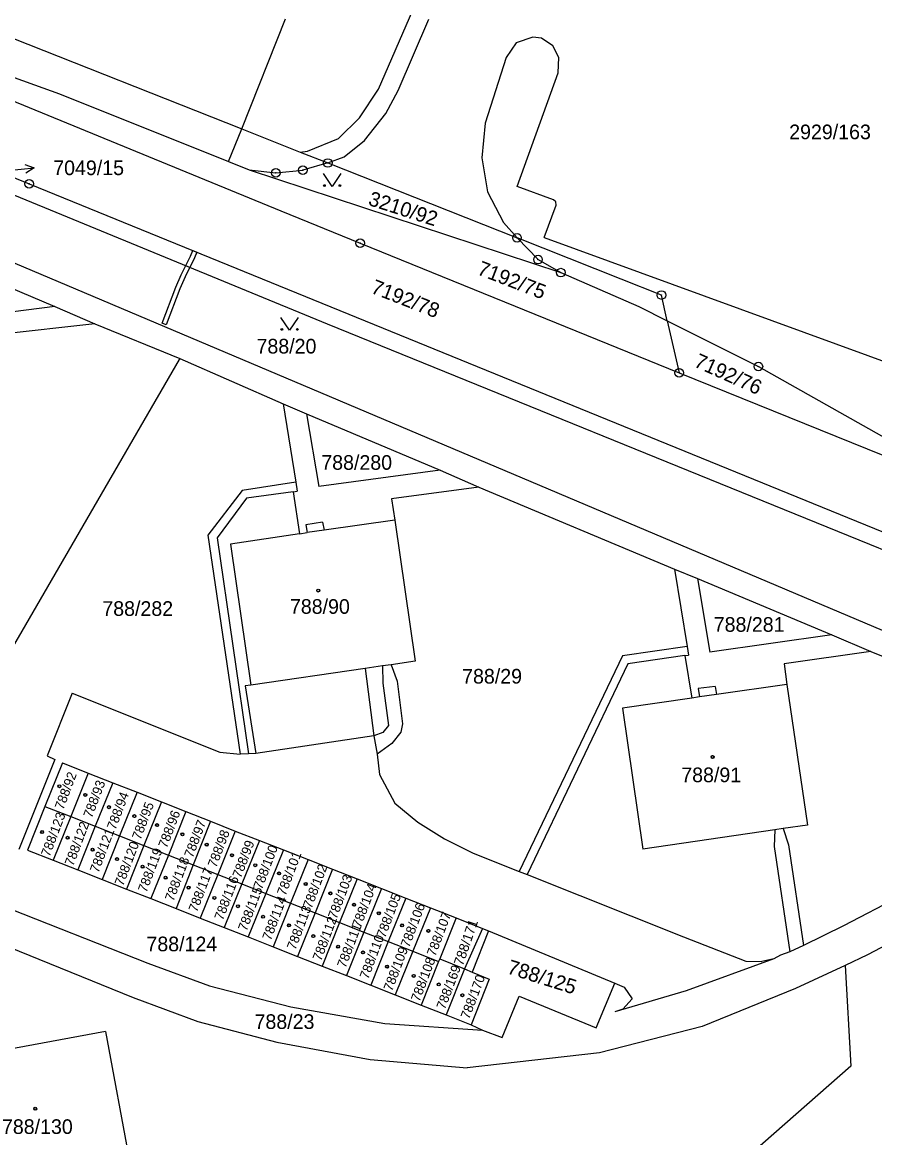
# Model space of a CAD drawing. Extents: x -593183 to -588034, y -1130415 to -1124994.
# Drawn here: x -591815.1 to -591716.1, y -1128430.1 to -1128300.6 of the extents above; entities that cross this region are included whole.
import ezdxf

# ---------------------------------------------------------------- set-up
doc = ezdxf.new("R2010")
doc.units = 0
for name, color, linetype in [('Vrstva 1', 7, 'Continuous'), ('Vrstva 16', 7, 'Continuous'), ('Vrstva 18', 7, 'Continuous'), ('Vrstva 19', 7, 'Continuous'), ('Vrstva 24', 7, 'Continuous'), ('Vrstva 25', 7, 'Continuous'), ('Vrstva 27', 7, 'Continuous'), ('Vrstva 4', 7, 'Continuous')]:
    doc.layers.add(name, color=color, linetype=linetype)

msp = doc.modelspace()

# ---------------------------------------------------------------- linework, layer by layer
at = {"layer": 'Vrstva 1'}
for p, q in [((-591955.86, -1128261.68), (-591814.3, -1128319.36)), ((-591931.29, -1128279.8), (-591692.48, -1128380.79)), ((-591864.93, -1128289.33), (-591810.78, -1128308.93)), ((-591849.68, -1128289.18), (-591789.62, -1128312.98)), ((-591841.44, -1128299.35), (-591785.07, -1128322.48)), ((-591789.62, -1128312.98), (-591784.53, -1128300.19)), ((-591771.45, -1128308.52), (-591767.88, -1128300.24)), ((-591757.76, -1128303), (-591758.9, -1128304.7)), ((-591755.84, -1128302.32), (-591757.76, -1128303)), ((-591754.8, -1128302.46), (-591755.84, -1128302.32)), ((-591753.51, -1128303.32), (-591754.8, -1128302.46)), ((-591752.79, -1128304.7), (-591753.51, -1128303.32)), ((-591758.9, -1128304.7), (-591761.37, -1128312.32)), ((-591752.9, -1128306.49), (-591752.79, -1128304.7)), ((-591757.64, -1128319.66), (-591752.9, -1128306.49)), ((-591772.9, -1128311.18), (-591771.45, -1128308.52)), ((-591845.27, -1128308.65), (-591779.71, -1128335.63)), ((-591810.78, -1128308.93), (-591791.16, -1128316.75)), ((-591775.38, -1128314.31), (-591772.9, -1128311.18)), ((-591761.37, -1128312.32), (-591761.76, -1128316.33)), ((-591791.16, -1128316.75), (-591789.62, -1128312.98)), ((-591789.62, -1128312.98), (-591782.83, -1128315.67)), ((-591777.71, -1128316.23), (-591775.38, -1128314.31)), ((-591782.83, -1128315.67), (-591779.62, -1128316.94)), ((-591779.62, -1128316.94), (-591777.71, -1128316.23)), ((-591761.76, -1128316.33), (-591761.1, -1128320.29)), ((-591791.16, -1128316.75), (-591788.74, -1128317.72)), ((-591779.62, -1128316.94), (-591757.66, -1128325.63)), ((-591788.74, -1128317.72), (-591752.58, -1128329.67)), ((-591814.3, -1128319.36), (-591692.65, -1128368.97)), ((-591753.41, -1128321.21), (-591757.64, -1128319.66)), ((-591761.1, -1128320.29), (-591759.21, -1128323.85)), ((-591753.14, -1128321.45), (-591753.41, -1128321.21)), ((-591753.12, -1128321.84), (-591753.14, -1128321.45)), ((-591785.07, -1128322.48), (-591775.88, -1128326.24)), ((-591754.51, -1128325.61), (-591753.12, -1128321.84)), ((-591759.21, -1128323.85), (-591757.66, -1128325.63)), ((-591775.88, -1128326.24), (-591738.82, -1128341.29)), ((-591745.55, -1128330.43), (-591757.66, -1128325.63)), ((-591754.51, -1128325.61), (-591693.43, -1128347.86)), ((-591827.42, -1128326.73), (-591811.33, -1128333.61)), ((-591752.58, -1128329.67), (-591743.52, -1128333.62)), ((-591740.9, -1128332.27), (-591745.55, -1128330.43)), ((-591740.21, -1128335.28), (-591740.9, -1128332.27)), ((-591811.33, -1128333.61), (-591806.67, -1128335.61)), ((-591743.52, -1128333.62), (-591740.21, -1128335.28)), ((-591806.67, -1128335.61), (-591817.81, -1128336.86)), ((-591806.67, -1128335.61), (-591796.81, -1128339.62)), ((-591779.71, -1128335.63), (-591717.97, -1128360.71)), ((-591740.21, -1128335.28), (-591738.82, -1128341.29)), ((-591740.21, -1128335.28), (-591729.64, -1128340.58)), ((-591796.81, -1128339.62), (-591796.87, -1128339.76)), ((-591796.81, -1128339.62), (-591784.8, -1128344.89)), ((-591796.87, -1128339.76), (-591824.71, -1128387.77)), ((-591729.64, -1128340.58), (-591712.55, -1128350.2)), ((-591738.82, -1128341.29), (-591715.2, -1128350.88)), ((-591784.8, -1128344.89), (-591782.1, -1128346.07)), ((-591784.8, -1128344.89), (-591783.34, -1128353.98)), ((-591782.1, -1128346.07), (-591766.57, -1128352.62)), ((-591766.57, -1128352.62), (-591762.08, -1128354.56)), ((-591783.63, -1128355.1), (-591783.2, -1128355.06)), ((-591783.63, -1128355.1), (-591782.9, -1128359.98)), ((-591783.34, -1128353.98), (-591783.2, -1128355.06)), ((-591762.08, -1128354.56), (-591772.22, -1128355.95)), ((-591762.08, -1128354.56), (-591739.38, -1128364.1)), ((-591772.22, -1128355.95), (-591771.86, -1128358.42)), ((-591780.25, -1128358.65), (-591782.16, -1128358.94)), ((-591782.16, -1128358.94), (-591782.01, -1128359.86)), ((-591780.25, -1128358.65), (-591780.04, -1128359.58)), ((-591771.86, -1128358.42), (-591780.04, -1128359.58)), ((-591771.86, -1128358.42), (-591769.48, -1128374.79)), ((-591782.9, -1128359.98), (-591790.93, -1128361.21)), ((-591782.9, -1128359.98), (-591782.01, -1128359.86)), ((-591790.93, -1128361.21), (-591788.56, -1128377.56)), ((-591717.97, -1128360.71), (-591690.26, -1128371.89)), ((-591739.38, -1128364.1), (-591736.72, -1128365.2)), ((-591739.38, -1128364.1), (-591737.91, -1128373.07)), ((-591736.72, -1128365.2), (-591721.12, -1128371.71)), ((-591721.12, -1128371.71), (-591716.57, -1128373.65)), ((-591737.91, -1128373.07), (-591737.75, -1128374.07)), ((-591738.16, -1128374.13), (-591737.75, -1128374.07)), ((-591738.16, -1128374.13), (-591737.35, -1128379.07)), ((-591716.57, -1128373.65), (-591726.66, -1128375.09)), ((-591716.57, -1128373.65), (-591693.55, -1128383.16)), ((-591775.28, -1128375.63), (-591788.56, -1128377.56)), ((-591773.28, -1128375.34), (-591775.28, -1128375.63)), ((-591775.28, -1128375.63), (-591774.3, -1128383.46)), ((-591772.26, -1128375.19), (-591773.28, -1128375.34)), ((-591769.48, -1128374.79), (-591772.26, -1128375.19)), ((-591726.66, -1128375.09), (-591726.33, -1128377.49)), ((-591809.3, -1128378.49), (-591812.2, -1128385.77)), ((-591809.3, -1128378.49), (-591792.14, -1128385.34)), ((-591788.56, -1128377.56), (-591789.2, -1128377.65)), ((-591789.2, -1128377.65), (-591787.97, -1128385.49)), ((-591734.65, -1128377.71), (-591736.62, -1128377.95)), ((-591736.62, -1128377.95), (-591736.46, -1128378.93)), ((-591734.65, -1128377.71), (-591734.51, -1128378.65)), ((-591726.33, -1128377.49), (-591734.51, -1128378.65)), ((-591726.33, -1128377.49), (-591723.94, -1128393.83)), ((-591737.35, -1128379.07), (-591745.42, -1128380.22)), ((-591736.46, -1128378.93), (-591737.35, -1128379.07)), ((-591745.42, -1128380.22), (-591743.06, -1128396.59)), ((-591774.3, -1128383.46), (-591773.89, -1128385.57)), ((-591811.3, -1128386.19), (-591815.5, -1128396.64)), ((-591812.2, -1128385.77), (-591811.3, -1128386.19)), ((-591792.14, -1128385.34), (-591789.81, -1128385.57)), ((-591788.82, -1128385.52), (-591789.81, -1128385.57)), ((-591787.97, -1128385.49), (-591788.82, -1128385.52)), ((-591773.89, -1128385.57), (-591773.63, -1128387.93)), ((-591810.43, -1128386.59), (-591812.46, -1128391.65)), ((-591810.43, -1128386.59), (-591807.43, -1128387.77)), ((-591807.43, -1128387.77), (-591809.46, -1128392.83)), ((-591807.43, -1128387.77), (-591804.59, -1128388.89)), ((-591773.63, -1128387.93), (-591771.84, -1128391.28)), ((-591804.59, -1128388.89), (-591806.62, -1128393.95)), ((-591804.59, -1128388.89), (-591801.77, -1128390)), ((-591801.77, -1128390), (-591803.8, -1128395.06)), ((-591801.77, -1128390), (-591798.94, -1128391.11)), ((-591798.94, -1128391.11), (-591800.97, -1128396.18)), ((-591798.94, -1128391.11), (-591796.1, -1128392.23)), ((-591771.84, -1128391.28), (-591769.16, -1128393.47)), ((-591812.46, -1128391.65), (-591814.49, -1128396.71)), ((-591812.46, -1128391.65), (-591809.46, -1128392.83)), ((-591796.1, -1128392.23), (-591798.13, -1128397.29)), ((-591796.1, -1128392.23), (-591793.26, -1128393.35)), ((-591809.46, -1128392.83), (-591811.5, -1128397.89)), ((-591809.46, -1128392.83), (-591806.62, -1128393.95)), ((-591806.62, -1128393.95), (-591808.66, -1128399.01)), ((-591806.62, -1128393.95), (-591803.8, -1128395.06)), ((-591793.26, -1128393.35), (-591795.25, -1128398.42)), ((-591793.26, -1128393.35), (-591790.36, -1128394.5)), ((-591769.16, -1128393.47), (-591766.06, -1128395.42)), ((-591723.94, -1128393.83), (-591726.75, -1128394.2)), ((-591803.8, -1128395.06), (-591805.82, -1128400.12)), ((-591803.8, -1128395.06), (-591800.97, -1128396.18)), ((-591790.36, -1128394.5), (-591792.4, -1128399.55)), ((-591790.36, -1128394.5), (-591787.57, -1128395.59)), ((-591727.73, -1128394.35), (-591743.06, -1128396.59)), ((-591726.75, -1128394.2), (-591727.73, -1128394.35)), ((-591800.97, -1128396.18), (-591802.99, -1128401.24)), ((-591800.97, -1128396.18), (-591798.13, -1128397.29)), ((-591787.57, -1128395.59), (-591789.61, -1128400.64)), ((-591787.57, -1128395.59), (-591784.78, -1128396.69)), ((-591766.06, -1128395.42), (-591762.73, -1128397.07)), ((-591843.22, -1128397.22), (-591802.21, -1128413.82)), ((-591814.49, -1128396.71), (-591811.5, -1128397.89)), ((-591811.5, -1128397.89), (-591808.66, -1128399.01)), ((-591798.13, -1128397.29), (-591800.16, -1128402.35)), ((-591798.13, -1128397.29), (-591795.25, -1128398.42)), ((-591784.78, -1128396.69), (-591786.82, -1128401.74)), ((-591784.78, -1128396.69), (-591781.92, -1128397.82)), ((-591781.92, -1128397.82), (-591783.94, -1128402.88)), ((-591781.92, -1128397.82), (-591779.07, -1128398.94)), ((-591762.73, -1128397.07), (-591757.39, -1128399.2)), ((-591808.66, -1128399.01), (-591805.82, -1128400.12)), ((-591795.25, -1128398.42), (-591797.24, -1128403.5)), ((-591795.25, -1128398.42), (-591792.4, -1128399.55)), ((-591779.07, -1128398.94), (-591781.1, -1128404)), ((-591779.07, -1128398.94), (-591776.23, -1128400.06)), ((-591757.39, -1128399.2), (-591756.48, -1128399.56)), ((-591825.32, -1128400.06), (-591800.51, -1128409.83)), ((-591805.82, -1128400.12), (-591802.99, -1128401.24)), ((-591792.4, -1128399.55), (-591794.44, -1128404.6)), ((-591792.4, -1128399.55), (-591789.61, -1128400.64)), ((-591776.23, -1128400.06), (-591778.25, -1128405.12)), ((-591776.23, -1128400.06), (-591773.4, -1128401.18)), ((-591756.48, -1128399.56), (-591738.34, -1128406.79)), ((-591802.99, -1128401.24), (-591800.16, -1128402.35)), ((-591789.61, -1128400.64), (-591791.65, -1128405.7)), ((-591789.61, -1128400.64), (-591786.82, -1128401.74)), ((-591786.82, -1128401.74), (-591788.87, -1128406.8)), ((-591786.82, -1128401.74), (-591783.94, -1128402.88)), ((-591773.4, -1128401.18), (-591775.43, -1128406.23)), ((-591773.4, -1128401.18), (-591770.57, -1128402.29)), ((-591712.43, -1128401.69), (-591719.74, -1128405.5)), ((-591800.16, -1128402.35), (-591797.24, -1128403.5)), ((-591783.94, -1128402.88), (-591785.97, -1128407.94)), ((-591783.94, -1128402.88), (-591781.1, -1128404)), ((-591770.57, -1128402.29), (-591772.6, -1128407.34)), ((-591770.57, -1128402.29), (-591767.72, -1128403.41)), ((-591797.24, -1128403.5), (-591794.44, -1128404.6)), ((-591781.1, -1128404), (-591783.13, -1128409.06)), ((-591781.1, -1128404), (-591778.25, -1128405.12)), ((-591767.72, -1128403.41), (-591769.76, -1128408.46)), ((-591767.72, -1128403.41), (-591764.73, -1128404.59)), ((-591794.44, -1128404.6), (-591791.65, -1128405.7)), ((-591791.65, -1128405.7), (-591788.87, -1128406.8)), ((-591778.25, -1128405.12), (-591780.28, -1128410.18)), ((-591778.25, -1128405.12), (-591775.43, -1128406.23)), ((-591764.73, -1128404.59), (-591766.63, -1128409.33)), ((-591764.73, -1128404.59), (-591761.66, -1128405.8)), ((-591719.74, -1128405.5), (-591724.41, -1128407.8)), ((-591709.68, -1128405.05), (-591716.97, -1128408.88)), ((-591788.87, -1128406.8), (-591785.97, -1128407.94)), ((-591775.43, -1128406.23), (-591777.46, -1128411.29)), ((-591775.43, -1128406.23), (-591772.6, -1128407.34)), ((-591760.96, -1128406.08), (-591762.85, -1128410.88)), ((-591761.66, -1128405.8), (-591760.96, -1128406.08)), ((-591760.96, -1128406.08), (-591746.32, -1128412.15)), ((-591738.34, -1128406.79), (-591731.08, -1128409.61)), ((-591785.97, -1128407.94), (-591783.13, -1128409.06)), ((-591772.6, -1128407.34), (-591774.63, -1128412.4)), ((-591772.6, -1128407.34), (-591769.76, -1128408.46)), ((-591724.41, -1128407.8), (-591725.99, -1128408.51)), ((-591783.13, -1128409.06), (-591780.28, -1128410.18)), ((-591769.76, -1128408.46), (-591771.8, -1128413.52)), ((-591769.76, -1128408.46), (-591766.76, -1128409.64)), ((-591766.63, -1128409.33), (-591766.76, -1128409.64)), ((-591766.63, -1128409.33), (-591763.76, -1128410.51)), ((-591727.85, -1128409.32), (-591738.03, -1128413.06)), ((-591727.85, -1128409.32), (-591729.22, -1128409.65)), ((-591727.07, -1128408.93), (-591727.85, -1128409.32)), ((-591725.99, -1128408.51), (-591727.07, -1128408.93)), ((-591716.97, -1128408.88), (-591719.58, -1128410.1)), ((-591800.51, -1128409.83), (-591793.37, -1128412.46)), ((-591780.28, -1128410.18), (-591777.46, -1128411.29)), ((-591766.76, -1128409.64), (-591768.8, -1128414.7)), ((-591763.76, -1128410.51), (-591765.9, -1128415.84)), ((-591763.76, -1128410.51), (-591762.85, -1128410.88)), ((-591762.85, -1128410.88), (-591760.9, -1128411.69)), ((-591731.08, -1128409.61), (-591729.22, -1128409.65)), ((-591719.58, -1128410.1), (-591725.34, -1128412.78)), ((-591719.58, -1128410.1), (-591718.9, -1128421.81)), ((-591777.46, -1128411.29), (-591774.63, -1128412.4)), ((-591760.9, -1128411.69), (-591762.98, -1128416.99)), ((-591748.48, -1128417.35), (-591746.32, -1128412.15)), ((-591746.32, -1128412.15), (-591745.22, -1128412.61)), ((-591793.37, -1128412.46), (-591783.9, -1128414.93)), ((-591774.63, -1128412.4), (-591771.8, -1128413.52)), ((-591738.03, -1128413.06), (-591746.3, -1128415.5)), ((-591745.22, -1128412.61), (-591744.29, -1128413.99)), ((-591725.34, -1128412.78), (-591736.16, -1128417.21)), ((-591802.21, -1128413.82), (-591794.72, -1128416.6)), ((-591771.8, -1128413.52), (-591768.8, -1128414.7)), ((-591768.8, -1128414.7), (-591765.9, -1128415.84)), ((-591759.39, -1128418.48), (-591757.39, -1128413.66)), ((-591757.39, -1128413.66), (-591748.48, -1128417.35)), ((-591744.29, -1128413.99), (-591745.39, -1128415.18)), ((-591783.9, -1128414.93), (-591773.02, -1128416.83)), ((-591765.9, -1128415.84), (-591762.98, -1128416.99)), ((-591745.39, -1128415.18), (-591746.3, -1128415.5)), ((-591794.72, -1128416.6), (-591785.55, -1128419)), ((-591773.02, -1128416.83), (-591761.67, -1128417.64)), ((-591762.98, -1128416.99), (-591761.67, -1128417.64)), ((-591736.16, -1128417.21), (-591748.09, -1128420.24)), ((-591805.43, -1128417.78), (-591824.42, -1128421.28)), ((-591805.43, -1128417.78), (-591802.43, -1128434.06)), ((-591761.67, -1128417.64), (-591759.39, -1128418.48)), ((-591785.55, -1128419), (-591774.71, -1128421.01)), ((-591774.71, -1128421.01), (-591763.45, -1128422.01)), ((-591748.09, -1128420.24), (-591763.45, -1128422.01)), ((-591718.9, -1128421.81), (-591734.52, -1128435.48))]:
    msp.add_line(p, q, dxfattribs=at)
at = {"layer": 'Vrstva 24'}
for centre, radius in [((-591785.67, -1128318.07), 0.5), ((-591782.51, -1128317.76), 0.5), ((-591779.62, -1128316.94), 0.5), ((-591779.62, -1128316.94), 0.0327), ((-591814.3, -1128319.36), 0.5), ((-591785.67, -1128318.07), 0.0327), ((-591782.51, -1128317.76), 0.0327), ((-591814.3, -1128319.36), 0.0327), ((-591757.66, -1128325.63), 0.5), ((-591775.88, -1128326.24), 0.5), ((-591775.88, -1128326.24), 0.0327), ((-591757.66, -1128325.63), 0.0327), ((-591755.22, -1128328.16), 0.5), ((-591755.22, -1128328.16), 0.0327), ((-591752.58, -1128329.67), 0.5), ((-591752.58, -1128329.67), 0.0327), ((-591740.9, -1128332.27), 0.5), ((-591740.9, -1128332.27), 0.0327), ((-591738.82, -1128341.29), 0.5), ((-591729.64, -1128340.58), 0.5), ((-591729.64, -1128340.58), 0.0327), ((-591738.82, -1128341.29), 0.0327)]:
    msp.add_circle(centre, radius, dxfattribs=at)
at = {"layer": 'Vrstva 25'}
msp.add_line((-591816.72, -1128317.81), (-591813.73, -1128317.52), dxfattribs=at)
for points in [[(-591814.78, -1128317.12), (-591813.73, -1128317.52), (-591814.68, -1128318.11)], [(-591778.12, -1128318.16), (-591779.12, -1128319.66), (-591780.12, -1128318.16)], [(-591783.06, -1128334.86), (-591784.06, -1128336.36), (-591785.06, -1128334.86)]]:
    msp.add_lwpolyline(points, dxfattribs=at)
for centre, radius in [((-591780.02, -1128319.56), 0.1), ((-591778.22, -1128319.56), 0.1), ((-591784.96, -1128336.26), 0.1), ((-591783.16, -1128336.26), 0.1), ((-591780.74, -1128366.58), 0.175), ((-591780.74, -1128366.58), 0.15), ((-591734.95, -1128385.9), 0.175), ((-591734.95, -1128385.9), 0.15), ((-591810.78, -1128389.3), 0.175), ((-591810.78, -1128389.3), 0.15), ((-591807.78, -1128390.31), 0.175), ((-591807.78, -1128390.31), 0.15), ((-591805.04, -1128391.73), 0.175), ((-591805.04, -1128391.73), 0.15), ((-591802.08, -1128392.77), 0.175), ((-591802.08, -1128392.77), 0.15), ((-591799.45, -1128393.81), 0.175), ((-591799.45, -1128393.81), 0.15), ((-591812.79, -1128394.62), 0.175), ((-591812.79, -1128394.62), 0.15), ((-591809.84, -1128395.28), 0.175), ((-591809.84, -1128395.28), 0.15), ((-591796.5, -1128394.88), 0.175), ((-591796.5, -1128394.88), 0.15), ((-591806.93, -1128396.67), 0.175), ((-591806.93, -1128396.67), 0.15), ((-591793.68, -1128396.08), 0.175), ((-591793.68, -1128396.08), 0.15), ((-591804.09, -1128397.76), 0.175), ((-591804.09, -1128397.76), 0.15), ((-591790.75, -1128397.31), 0.175), ((-591790.75, -1128397.31), 0.15), ((-591801.13, -1128398.64), 0.175), ((-591801.13, -1128398.64), 0.15), ((-591788.05, -1128398.47), 0.175), ((-591788.05, -1128398.47), 0.15), ((-591785.29, -1128399.42), 0.175), ((-591798.46, -1128399.92), 0.175), ((-591798.46, -1128399.92), 0.15), ((-591785.29, -1128399.42), 0.15), ((-591782.19, -1128400.65), 0.175), ((-591782.19, -1128400.65), 0.15), ((-591795.79, -1128401.07), 0.175), ((-591795.79, -1128401.07), 0.15), ((-591779.33, -1128401.74), 0.175), ((-591779.33, -1128401.74), 0.15), ((-591792.78, -1128402.26), 0.175), ((-591792.78, -1128402.26), 0.15), ((-591790.06, -1128403.23), 0.175), ((-591790.06, -1128403.23), 0.15), ((-591776.58, -1128403.06), 0.175), ((-591776.58, -1128403.06), 0.15), ((-591787.13, -1128404.46), 0.175), ((-591787.13, -1128404.46), 0.15), ((-591773.7, -1128404.05), 0.175), ((-591773.7, -1128404.05), 0.15), ((-591784.13, -1128405.45), 0.175), ((-591784.13, -1128405.45), 0.15), ((-591771, -1128405.45), 0.175), ((-591771, -1128405.45), 0.15), ((-591781.31, -1128406.7), 0.175), ((-591781.31, -1128406.7), 0.15), ((-591767.95, -1128406.09), 0.175), ((-591767.95, -1128406.09), 0.15), ((-591778.43, -1128407.93), 0.175), ((-591778.43, -1128407.93), 0.15), ((-591775.54, -1128408.6), 0.175), ((-591775.54, -1128408.6), 0.15), ((-591772.75, -1128410.25), 0.175), ((-591772.75, -1128410.25), 0.15), ((-591769.65, -1128411.32), 0.175), ((-591769.65, -1128411.32), 0.15), ((-591766.74, -1128412.31), 0.175), ((-591766.74, -1128412.31), 0.15), ((-591764, -1128413.56), 0.175), ((-591764, -1128413.56), 0.15), ((-591813.59, -1128426.74), 0.175), ((-591813.59, -1128426.74), 0.15)]:
    msp.add_circle(centre, radius, dxfattribs=at)
at = {"layer": 'Vrstva 27'}
for p, q in [((-591796.63, -1128329.94), (-591795.55, -1128327.74)), ((-591795.09, -1128327.94), (-591796.17, -1128330.16)), ((-591795.55, -1128327.74), (-591795.3, -1128327.11)), ((-591795.3, -1128327.11), (-591794.84, -1128327.3)), ((-591794.84, -1128327.3), (-591795.09, -1128327.94)), ((-591797.26, -1128331.36), (-591796.63, -1128329.94)), ((-591796.17, -1128330.16), (-591796.8, -1128331.56)), ((-591798.84, -1128335.55), (-591797.26, -1128331.36)), ((-591796.8, -1128331.56), (-591798.38, -1128335.73)), ((-591798.38, -1128335.73), (-591798.84, -1128335.55))]:
    msp.add_line(p, q, dxfattribs=at)
at = {"layer": 'Vrstva 4'}
for p, q in [((-591773.73, -1128308.38), (-591769.77, -1128299.21)), ((-591775.96, -1128311.71), (-591773.73, -1128308.38)), ((-591778.39, -1128314.1), (-591775.96, -1128311.71)), ((-591782, -1128315.55), (-591778.39, -1128314.1)), ((-591782.83, -1128315.67), (-591782, -1128315.55)), ((-591779.62, -1128316.94), (-591782.51, -1128317.76)), ((-591788.74, -1128317.72), (-591785.67, -1128318.07)), ((-591785.67, -1128318.07), (-591782.51, -1128317.76)), ((-591757.66, -1128325.63), (-591755.22, -1128328.16)), ((-591755.22, -1128328.16), (-591752.58, -1128329.67)), ((-591811.33, -1128333.61), (-591826.2, -1128335.45)), ((-591782.1, -1128346.07), (-591780.66, -1128354.5)), ((-591766.57, -1128352.62), (-591780.66, -1128354.5)), ((-591789.57, -1128354.96), (-591793.56, -1128360.16)), ((-591783.34, -1128353.98), (-591789.57, -1128354.96)), ((-591783.63, -1128355.1), (-591789.05, -1128355.87)), ((-591789.05, -1128355.87), (-591792.45, -1128360.47)), ((-591793.56, -1128360.16), (-591789.81, -1128385.57)), ((-591780.04, -1128359.58), (-591782.01, -1128359.86)), ((-591792.45, -1128360.47), (-591788.82, -1128385.52)), ((-591736.72, -1128365.2), (-591735.27, -1128373.75)), ((-591721.12, -1128371.71), (-591735.27, -1128373.75)), ((-591737.91, -1128373.07), (-591745.43, -1128374.15)), ((-591745.43, -1128374.15), (-591757.39, -1128399.2)), ((-591738.16, -1128374.13), (-591744.78, -1128375.07)), ((-591773.28, -1128375.34), (-591773.22, -1128377.32)), ((-591772.26, -1128375.19), (-591771.59, -1128377.11)), ((-591744.78, -1128375.07), (-591756.48, -1128399.56)), ((-591771.59, -1128377.11), (-591770.96, -1128382.05)), ((-591773.22, -1128377.32), (-591772.57, -1128382.24)), ((-591734.51, -1128378.65), (-591736.46, -1128378.93)), ((-591772.57, -1128382.24), (-591773.25, -1128383.07)), ((-591770.96, -1128382.05), (-591771.13, -1128383.01)), ((-591774.3, -1128383.46), (-591787.97, -1128385.49)), ((-591773.25, -1128383.07), (-591774.3, -1128383.46)), ((-591771.13, -1128383.01), (-591772.2, -1128384.35)), ((-591772.2, -1128384.35), (-591773.89, -1128385.57)), ((-591727.73, -1128394.35), (-591727.79, -1128396.29)), ((-591726.75, -1128394.2), (-591726.13, -1128396.1)), ((-591727.79, -1128396.29), (-591725.99, -1128408.51)), ((-591726.13, -1128396.1), (-591724.41, -1128407.8)), ((-591761.66, -1128405.8), (-591763.76, -1128410.51))]:
    msp.add_line(p, q, dxfattribs=at)

# ---------------------------------------------------------------- texts
at = {"layer": 'Vrstva 16'}
msp.add_text('7049/15', height=1.7, dxfattribs=at).set_placement((-591811.5, -1128318.35))
at = {"layer": 'Vrstva 18'}
for s, p in [('2929/163', (-591726.06, -1128314.18)), ('788/20', (-591787.9, -1128339.06)), ('788/280', (-591780.38, -1128352.56)), ('788/282', (-591805.8, -1128369.52)), ('788/281', (-591734.82, -1128371.37)), ('788/29', (-591764.03, -1128377.38)), ('788/124', (-591800.68, -1128408.46)), ('788/23', (-591788.13, -1128417.48))]:
    msp.add_text(s, height=1.7, dxfattribs=at).set_placement(p)
for s, height, rotation, p in [('3210/92', 1.7, 342.1699, (-591775.03, -1128321.79)), ('7192/75', 1.7, 338.9517, (-591762.39, -1128329.84)), ('7192/78', 1.7, 338.6898, (-591774.73, -1128331.99)), ('7192/76', 1.7, 335.8143, (-591737.22, -1128340.53)), ('788/171', 1.14, 71.0296, (-591763.95, -1128410.22)), ('788/125', 1.7, 342.4899, (-591758.92, -1128411.01))]:
    msp.add_text(s, height=height, rotation=rotation, dxfattribs=at).set_placement(p)
at = {"layer": 'Vrstva 19'}
for s, p in [('788/90', (-591784.02, -1128369.28)), ('788/91', (-591738.59, -1128388.83)), ('788/130', (-591817.45, -1128429.67))]:
    msp.add_text(s, height=1.7, dxfattribs=at).set_placement(p)
for s, p in [('788/92', (-591810.34, -1128392.11)), ('788/93', (-591807.02, -1128393.07)), ('788/94', (-591804.28, -1128394.44)), ('788/95', (-591801.37, -1128395.6)), ('788/123', (-591811.93, -1128397.56)), ('788/96', (-591798.32, -1128396.57)), ('788/122', (-591809.19, -1128398.65)), ('788/97', (-591795.31, -1128397.69)), ('788/121', (-591806.26, -1128399.43)), ('788/98', (-591792.58, -1128398.83)), ('788/120', (-591803.39, -1128400.96)), ('788/119', (-591800.68, -1128401.71)), ('788/99', (-591789.71, -1128400.05)), ('788/100', (-591787.28, -1128401.37)), ('788/118', (-591797.55, -1128402.74)), ('788/101', (-591784.54, -1128402.09)), ('788/117', (-591794.81, -1128404)), ('788/102', (-591781.52, -1128403.58)), ('788/116', (-591791.81, -1128404.95)), ('788/103', (-591778.62, -1128404.8)), ('788/115', (-591789.06, -1128406.2)), ('788/104', (-591775.82, -1128405.82)), ('788/105', (-591772.98, -1128406.98)), ('788/114', (-591786.25, -1128407.29)), ('788/106', (-591770.18, -1128408.1)), ('788/113', (-591783.39, -1128408.38)), ('788/107', (-591767.15, -1128409.13)), ('788/112', (-591780.41, -1128409.67)), ('788/111', (-591777.56, -1128410.48)), ('788/110', (-591774.94, -1128411.78)), ('788/109', (-591772.17, -1128413.18)), ('788/108', (-591768.99, -1128414.4)), ('788/169', (-591766.03, -1128415.3)), ('788/170', (-591763.22, -1128416.42))]:
    msp.add_text(s, height=1.1, rotation=69.2277, dxfattribs=at).set_placement(p)

doc.saveas('drawing.dxf')
